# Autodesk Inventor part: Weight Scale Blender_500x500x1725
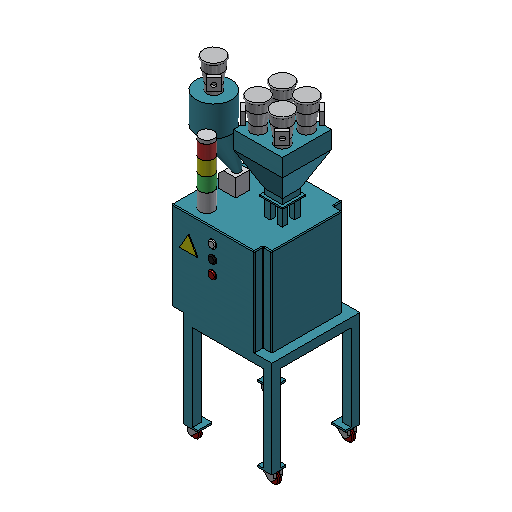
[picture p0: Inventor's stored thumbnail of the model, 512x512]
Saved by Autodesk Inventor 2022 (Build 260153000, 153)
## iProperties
RuleStatus: InUse
Created: 2013-08
Material: 一般
Document SubType Name: Modeling
Density: 1 g/cm^3
Appearance: 既定
Part Number: Weight Scale Blender_500x500x1725
Key Parameters: Length=500.000 mm;Width=500.000 mm;Height=1725.000 mm;
Author: Autodesk, Inc.
Title: Weight Scale Blender
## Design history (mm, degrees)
sketch "Sketch1"
  geometry: L1 (250, -250)-(-250, -250); L2 (-250, -250)-(-250, 250); L3 (-250, 250)-(250, 250); L4 (250, 250)-(250, -250); L5 (250, -250)-(-250, 250); L6 (-250, -250)-(250, 250); L7 (250, -250)-(170, -250); L8 (170, -250)-(170, -170); L9 (170, -170)-(250, -170); L10 (250, -170)-(250, -250); L11 (-250, -250)-(-170, -250); L12 (-170, -250)-(-170, -170); L13 (-170, -170)-(-250, -170); L14 (-250, -170)-(-250, -250); L15 (250, 250)-(170, 250); L16 (170, 250)-(170, 170); L17 (170, 170)-(250, 170); L18 (250, 170)-(250, 250); L19 (-250, 250)-(-170, 250); L20 (-170, 250)-(-170, 170); L21 (-170, 170)-(-250, 170); L22 (-250, 170)-(-250, 250); L23 (-350, 0)-(350, 0) reference; L24 (0, -1400)-(0, 1400) reference; 2 further points
  constraints: 44 end point, 10 parallel, 5 horizontal, 5 midpoint, 5 perpendicular
  dimensions: "d6" = 500 distance of L2.end L3.end (derived); "d7" = 500 distance of L1.end L2.end (derived); "d8" = 80 distance of L7.end L8.end; "d9" = 80 distance of L8.end L9.end; "d10" = 80 distance of L16.end L17.end; "d11" = 80 distance of L15.end L16.end; "d12" = 80 distance of L19.end L20.end; "d13" = 80 distance of L20.end L21.end; "d14" = 80 distance of L12.end L13.end; "d15" = 80 distance of L11.end L12.end
extrude "Extrusion1" new body sketch "Sketch1" distance "d16" = 10; taper "d17" = 0 deg
sketch "Sketch3"
  geometry: L1 (-250, -250)-(-170, -250) reference; L2 (-170, -250)-(-170, -170) reference; L3 (-170, -170)-(-250, -170) reference; L4 (-250, -170)-(-250, -250) reference; L5 (250, -250)-(170, -250) reference; L6 (250, -170)-(250, -250) reference; L7 (170, -170)-(250, -170) reference; L8 (170, -250)-(170, -170) reference; L9 (250, 250)-(170, 250) reference; L10 (170, 250)-(170, 170) reference; L11 (170, 170)-(250, 170) reference; L12 (250, 170)-(250, 250) reference; L13 (-250, 250)-(-200, 250); L14 (-200, 250)-(-200, 200); L15 (-200, 200)-(-250, 200); L16 (-250, 200)-(-250, 250); L17 (-250, -250)-(-200, -250); L18 (-200, -250)-(-200, -200); L19 (-200, -200)-(-250, -200); L20 (-250, -200)-(-250, -250); L21 (250, -250)-(200, -250); L22 (200, -250)-(200, -200); L23 (200, -200)-(250, -200); L24 (250, -200)-(250, -250); L25 (250, 250)-(200, 250); L26 (200, 250)-(200, 200); L27 (200, 200)-(250, 200); L28 (250, 200)-(250, 250); 1 further point
  constraints: 32 end point, 8 parallel, 4 horizontal, 4 perpendicular
  dimensions: "d18" = 50 distance of L22.end L23.end; "d19" = 50 distance of L21.end L22.end; "d20" = 50 distance of L26.end L27.end; "d21" = 50 distance of L25.end L26.end; "d22" = 50 distance of L14.end L15.end; "d23" = 50 distance of L13.end L14.end; "d24" = 50 distance of L18.end L19.end; "d25" = 50 distance of L17.end L18.end
extrude "Extrusion2" join sketch "Sketch3" distance "d26" = 500 (derived); taper "d27" = 0 deg
sketch "Sketch4"
  geometry: L1 (250, 250)-(200, 250) reference; L2 (200, 250)-(200, 200) reference; L3 (200, 200)-(250, 200) reference; L4 (250, 200)-(250, 250) reference; L5 (-250, -250)-(250, -250); L6 (250, -250)-(250, 250); L7 (250, 250)-(-250, 250); L8 (-250, 250)-(-250, -250); 1 further point
  constraints: 8 end point, 2 parallel, 1 horizontal, 1 perpendicular
extrude "Extrusion3" join sketch "Sketch4" distance "d28" = 50; taper "d29" = 0 deg
sketch "Sketch8"
  geometry: L1 (-250, -250)-(250, -250) reference; L2 (250, -250)-(250, 250) reference; L3 (250, 250)-(-250, 250) reference; L4 (-250, 250)-(-250, -250) reference; L5 (-320, 250)-(200, 250); L6 (200, 250)-(200, -250); L7 (200, -250)-(-320, -250); L8 (-320, -250)-(-320, 250); 1 further point
  constraints: 8 end point, 2 parallel, 1 collinear, 1 horizontal, 1 perpendicular, 1 point on line
  dimensions: "d30" = 70 distance between parallel lines of L8 L4; "d31" = 50 distance between parallel lines of L6 L2
extrude "Extrusion4" join sketch "Sketch8" distance "d32" = 500; taper "d33" = 0 deg
sketch "Sketch9"
  geometry: L1 (200, 250)-(150, 250); L2 (150, 250)-(150, 200); L3 (150, 200)-(200, 200); L4 (200, 200)-(200, 250); L5 (200, -250)-(150, -250); L6 (150, -250)-(150, -200); L7 (150, -200)-(200, -200); L8 (200, -200)-(200, -250); 1 further point
  constraints: 16 end point, 4 parallel, 2 horizontal, 2 perpendicular
  dimensions: "d34" = 50 distance of L2.end L3.end; "d35" = 50 distance of L1.end L2.end; "d36" = 50 distance of L6.end L7.end; "d37" = 50 distance of L5.end L6.end
extrude "Extrusion5" cut sketch "Sketch9" stored distance "d38" = 500000; taper "d39" = 0 deg
fillet "Fillet1" dims "d40" = 5
sketch "Sketch10"
  geometry: L1 (395, 1045)-(395, 550) reference; L2 (-65, 1045)-(395, 1045) reference; L3 (500, 0)-(500, 550) reference; L4 (165, 1045)-(165, 550); L5 (-65, 550)-(395, 550); C1 r 22.5 at (165, 970); C2 r 22.5 at (165, 895); C3 r 22.5 at (165, 820); 1 further point
  constraints: 4 end point, 3 centre point, 3 point on line, 2 midpoint, 2 parallel, 1 perpendicular
  dimensions: "d41" = 45 diameter of C1; "d42" = 45 diameter of C2; "d43" = 45 diameter of C3; "d44" = 75 distance from line of C1.centre L2; "d45" = 75 distance of C1.centre C2.centre; "d46" = 75 distance of C2.centre C3.centre
extrude "Extrusion6" join sketch "Sketch10" distance "d47" = 10; taper "d48" = 0 deg
extrude "Extrusion7" join sketch "Sketch10" distance "d49" = 10; taper "d50" = 0 deg
extrude "Extrusion8" join sketch "Sketch10" distance "d51" = 10; taper "d52" = 0 deg
fillet "Fillet2" dims "d53" = 5
fillet "Fillet3" dims "d54" = 5
fillet "Fillet4" dims "d55" = 5
sketch "Sketch11"
  geometry: L1 (-315, -245)-(-315, 245) reference; L2 (195, 195)-(195, -195) reference; L3 (-315, 0)-(195, 0); L4 (10, 50)-(110, 50); L5 (110, 50)-(110, -50); L6 (110, -50)-(10, -50); L7 (10, -50)-(10, 50); L8 (10, 50)-(110, -50); L9 (110, 50)-(10, -50); 2 further points
  constraints: 14 end point, 4 midpoint, 2 parallel, 1 horizontal, 1 perpendicular, 1 point on line
  dimensions: "d56" = 100 distance of L4.start L4.end; "d57" = 100 distance of L4.end L5.end; "d58" = 85 distance between parallel lines of L5 L2
extrude "Extrusion9" join sketch "Sketch11" distance "d59" = 110; taper "d60" = 0 deg
sketch "Sketch12"
  geometry: L1 (110, 50)-(10, 50) reference; L2 (10, 50)-(10, -50) reference; L3 (10, -50)-(110, -50) reference; L4 (110, -50)-(110, 50) reference; L5 (-5, 65)-(125, 65); L6 (125, 65)-(125, -65); L7 (125, -65)-(-5, -65); L8 (-5, -65)-(-5, 65); 1 further point
  constraints: 8 end point, 3 other
  dimensions: "d61" = 15 distance between parallel lines of L1 L5
extrude "Extrusion10" join sketch "Sketch12" distance "d62" = 8; taper "d63" = 0 deg
sketch "Sketch13"
  geometry: L1 (-5, 65)-(125, 65) reference; L2 (-5, -65)-(-5, 65) reference; L3 (125, -65)-(-5, -65) reference; L4 (125, 65)-(125, -65) reference; L5 (110, 50)-(10, 50); L6 (10, 50)-(10, -50); L7 (10, -50)-(110, -50); L8 (110, -50)-(110, 50); 1 further point
  constraints: 8 end point, 3 other
  dimensions: "d64" = 15 distance between parallel lines of L1 L5
extrude "Extrusion11" join sketch "Sketch13" distance "d65" = 30; taper "d66" = 0 deg
sketch "Sketch14"
  geometry: L1 (110, 50)-(10, 50) reference; L2 (10, 50)-(10, -50) reference; L3 (10, -50)-(110, -50) reference; L4 (110, -50)-(110, 50) reference; 1 further point
extrude "Extrusion12" join sketch "Sketch14" distance "d67" = 190.8125; taper "d68" = 25 deg
sketch "Sketch15"
  geometry: L1 (198.977, 138.977)-(198.977, -138.977) reference; L2 (-78.977, 138.977)-(198.977, 138.977) reference; L3 (-78.977, -138.977)-(-78.977, 138.977) reference; L4 (198.977, -138.977)-(-78.977, -138.977) reference; 1 further point
extrude "Extrusion13" join sketch "Sketch15" distance "d69" = 100; taper "d70" = 0 deg
sketch "Sketch16"
  geometry: L1 (110, 50)-(110, -50) reference; L2 (110, -50)-(10, -50) reference; L3 (10, -50)-(10, 50) reference; L4 (10, 50)-(110, 50) reference; L5 (155, 195)-(195, 195) reference; L6 (80, 50)-(80, 20); L7 (80, 20)-(110, 20); L8 (110, 20)-(110, -20); L9 (110, -20)-(80, -20); L10 (80, -20)-(80, -50); L11 (80, -50)-(40, -50); L12 (40, -50)-(40, -20); L13 (40, -20)-(10, -20); L14 (10, -20)-(10, 20); L15 (10, 20)-(40, 20); L16 (40, 20)-(40, 50); L17 (40, 50)-(80, 50); 1 further point
  constraints: 24 end point, 8 perpendicular, 8 point on line, 1 collinear
  dimensions: "d71" = 30 distance between parallel lines of L7 L4; "d72" = 30 distance between parallel lines of L2 L9; "d73" = 30 distance between parallel lines of L1 L10; "d74" = 30 distance between parallel lines of L3 L12; "d75" = 30 distance between parallel lines of L2 L13; "d76" = 30 distance between parallel lines of L4 L15; "d77" = 30 distance between parallel lines of L3 L16; "d78" = 30 distance between parallel lines of L1 L6
extrude "Extrusion14" cut sketch "Sketch16" stored distance "d79" = 114.2875; taper "d80" = 0 deg
sketch "Sketch17"
  geometry: L1 (-315, -245)-(-315, 245) reference; L2 (155, 195)-(195, 195) reference; L3 (-315, 0)-(-37.685, 0); L4 (-265, 40)-(-165, 40); L5 (-165, 40)-(-165, -40); L6 (-165, -40)-(-265, -40); L7 (-265, -40)-(-265, 40); L8 (-265, 40)-(-165, -40); L9 (-165, 40)-(-265, -40); 2 further points
  constraints: 14 end point, 3 midpoint, 3 parallel, 1 horizontal, 1 perpendicular, 1 point on line
  dimensions: "d81" = 100 distance of L4.start L4.end; "d82" = 80 distance of L4.end L5.end; "d83" = 50 distance between parallel lines of L1 L7
extrude "Extrusion15" join sketch "Sketch17" distance "d84" = 100; taper "d85" = 0 deg
chamfer "Chamfer1" distance "d86" = 30; stored, may be unused: second distance "d87" = 2, angle "d88" = 45 deg
sketch "Sketch18"
  geometry: L1 (-235, -40)-(-235, 40) reference; L2 (-235, 0)-(-165, 0); C1 r 22.5 at (-200, 0); 5 further points; 1 other entity
  constraints: 2 end point, 2 midpoint, 1 centre point, 2 other
  dimensions: "d89" = 45 diameter of C1
workplane "Work Plane1"
sketch "Sketch19"
  geometry: L1 (-200, 0)-(-594.488, 0); L2 (-320, 245)-(-320, -245) reference; C1 r 22.5 at (-200, 0) reference; C2 r 100 at (-330, 0); 1 further point
  constraints: 2 end point, 1 centre point, 1 horizontal, 1 point on line
  dimensions: "d91" = 200 diameter of C2; "d92" = 10 distance from line of L2 C2.centre
loft "Loft1" sketch "Sketch19" dims "d93" = 0, "d94" = 90 deg, "d95" = 0, "d96" = 90 deg
sketch "Sketch20"
  geometry: C1 r 100 at (0, 0) reference; 1 further point
extrude "Extrusion16" join sketch "Sketch20" stored distance "d97" = 150; taper "d98" = 0 deg
sketch "Sketch21"
  geometry: L1 (198.977, -138.977)-(198.977, 138.977) reference; L2 (198.977, 138.977)-(-78.977, 138.977) reference; L3 (-78.977, 138.977)-(-78.977, -138.977) reference; L4 (-78.977, -138.977)-(198.977, -138.977) reference; C1 r 40 at (-8.977, 68.977); C2 r 40 at (128.977, 68.977); C3 r 40 at (-8.977, -68.977); C4 r 40 at (128.977, -68.977); C5 r 100 at (-330, 0) reference; C6 r 40 at (-330, 0); 1 further point
  constraints: 5 centre point, 1 coincident
  dimensions: "d99" = 70 distance from line of L2 C1.centre; "d100" = 70 distance from line of L3 C1.centre; "d101" = 70 distance from line of L2 C2.centre; "d102" = 70 distance from line of L1 C2.centre; "d103" = 70 distance from line of L3 C3.centre; "d104" = 70 distance from line of L4 C3.centre; "d105" = 70 distance from line of L4 C4.centre; "d106" = 70 distance from line of L1 C4.centre; "d107" = 80 diameter of C1; "d108" = 80 diameter of C2; "d109" = 80 diameter of C3; "d110" = 80 diameter of C4; "d128" = 80 diameter of C6
extrude "Extrusion17" join sketch "Sketch21" distance "d111" = 40; taper "d112" = 0 deg
sketch "Sketch22"
  geometry: C1 r 40 at (0, 0) reference; C2 r 40 at (137.955, 0) reference; C3 r 40 at (0, -137.955) reference; C4 r 40 at (137.955, -137.955) reference; C5 r 40 at (-321.023, -68.977) reference; 1 further point
extrude "Extrusion18" join sketch "Sketch22" distance "d113" = 70; taper "d114" = 10 deg
sketch "Sketch23"
  geometry: C1 r 52.343 at (0, 0) reference; C2 r 52.343 at (137.955, 0) reference; C3 r 52.343 at (0, -137.955) reference; C4 r 52.343 at (137.955, -137.955) reference; C5 r 40 at (-321.023, -68.977) reference; C6 r 52.343 at (-321.023, -68.977) reference; 1 further point
extrude "Extrusion19" join sketch "Sketch23" distance "d115" = 60; taper "d116" = 0 deg
sketch "Sketch24"
  geometry: C1 r 52.343 at (0, 0) reference; C2 r 52.343 at (-137.955, 0) reference; C3 r 52.343 at (-137.955, -137.955) reference; C4 r 52.343 at (0, -137.955) reference; C5 r 62.343 at (-137.955, 0); C6 r 62.343 at (0, 0); C7 r 62.343 at (0, -137.955); C8 r 62.343 at (-137.955, -137.955); C9 r 52.343 at (-458.977, -68.977) reference; C10 r 62.343 at (-458.977, -68.977); 1 further point
  constraints: 5 centre point
  dimensions: "d117" = 10 radial gap between concentric circles of C2 C5; "d118" = 10 radial gap between concentric circles of C1 C6; "d119" = 10 radial gap between concentric circles of C4 C7; "d120" = 10 radial gap between concentric circles of C3 C8; "d129" = 10 radial gap between concentric circles of C9 C10
extrude "Extrusion20" join sketch "Sketch24" distance "d121" = 10; taper "d122" = 0 deg
sketch "Sketch25"
  geometry: L1 (500, 0)-(500, 550) reference; L2 (30, 950)-(-20, 863.397); L3 (-20, 863.397)-(80, 863.397); L4 (80, 863.397)-(30, 950); L5 (395, 1050)-(-65, 1050) reference; L6 (-70, 1045)-(-70, 550) reference; 1 further point
  constraints: 6 end point, 2 equal length, 1 perpendicular
  dimensions: "d123" = 100 distance of L2.end L3.end; "d124" = 100 distance from line of L5 L2.start; "d125" = 50 distance from line of L6 L2.end
extrude "Extrusion21" join sketch "Sketch25" distance "d126" = 5; taper "d127" = 0 deg
sketch "Sketch26"
  geometry: L1 (-320, 245)-(-320, -245) reference; L2 (-315, -250)-(145, -250) reference; C1 r 40 at (-200, -170); 1 further point
  constraints: 1 centre point
  dimensions: "d130" = 80 diameter of C1; "d131" = 120 distance from line of L1 C1.centre; "d132" = 80 distance from line of L2 C1.centre
extrude "Extrusion22" join sketch "Sketch26" distance "d133" = 100; taper "d134" = 0 deg
sketch "Sketch27"
  geometry: C1 r 40 at (0, 0) reference; 1 further point
extrude "Extrusion23" new body sketch "Sketch27" distance "d135" = 80; taper "d136" = 0 deg
sketch "Sketch28"
  geometry: C1 r 40 at (0, 0) reference; 1 further point
extrude "Extrusion24" new body sketch "Sketch28" distance "d137" = 80; taper "d138" = 0 deg
sketch "Sketch29"
  geometry: C1 r 40 at (0, 0) reference; 1 further point
extrude "Extrusion25" new body sketch "Sketch29" distance "d139" = 80; taper "d140" = 0 deg
sketch "Sketch30"
  geometry: C1 r 40 at (0, 0) reference; 1 further point
extrude "Extrusion26" new body sketch "Sketch30" distance "d141" = 20; taper "d142" = 0 deg
fillet "Fillet5" dims "d143" = 5
workplane "Work Plane2"
sketch "Sketch31"
  geometry: L1 (144.776, -127.203)-(187.203, -84.776); L2 (187.203, -84.776)-(201.345, -98.918); L3 (201.345, -98.918)-(158.918, -141.345); L4 (158.918, -141.345)-(144.776, -127.203); L5 (144.776, 127.203)-(187.203, 84.776); L6 (187.203, 84.776)-(201.345, 98.918); L7 (201.345, 98.918)-(158.918, 141.345); L8 (158.918, 141.345)-(144.776, 127.203); L9 (-314.201, -58.225)-(-271.775, -15.799); L10 (-271.775, -15.799)-(-257.633, -29.941); L11 (-257.633, -29.941)-(-300.059, -72.367); L12 (-300.059, -72.367)-(-314.201, -58.225); L13 (128.977, -68.977)-(282.8, -222.8); L14 (128.977, 68.977)-(242.144, 182.144); L15 (-8.977, 68.977)-(-133.35, 193.35); L16 (-8.977, -68.977)-(-76.387, -136.387); L17 (250, 250)-(145, 250) reference; L18 (145, 250)-(-315, 250) reference; L19 (-315, -250)-(145, -250) reference; L20 (-330, 0)-(-221.248, -108.752); L21 (-38.918, 141.345)-(-81.345, 98.918); L22 (-81.345, 98.918)-(-67.203, 84.776); L23 (-67.203, 84.776)-(-24.776, 127.203); L24 (-24.776, 127.203)-(-38.918, 141.345); L25 (-67.203, -84.776)-(-81.345, -98.918); L26 (-81.345, -98.918)-(-38.918, -141.345); L27 (-38.918, -141.345)-(-24.776, -127.203); L28 (-24.776, -127.203)-(-67.203, -84.776); C1 r 52.343 at (128.977, -68.977) reference; C2 r 40 at (128.977, -68.977) reference; C3 r 52.343 at (-8.977, -68.977) reference; C4 r 40 at (-8.977, -68.977) reference; C5 r 52.343 at (128.977, 68.977) reference; C6 r 40 at (128.977, 68.977) reference; C7 r 40 at (-8.977, 68.977) reference; C8 r 52.343 at (-8.977, 68.977) reference; C9 r 40 at (-8.977, 68.977) reference; C10 r 52.343 at (-330, 0) reference; C11 r 40 at (-330, 0) reference; 1 further point
  constraints: 50 end point, 10 parallel, 6 perpendicular, 5 tangent, 5 other
  dimensions: "d145" = 135 deg angle of L17 L14; "d146" = 45 deg angle of L18 L15; "d147" = 45 deg angle of L19 L16; "d148" = 45 deg angle of L19 L20; "d149" = 60 distance of L21.start L21.end; "d150" = 20 distance of L23.end L21.start; "d151" = 20 distance of L9.end L10.end; "d152" = 60 distance of L10.end L11.end; "d155" = 60 distance of L25.end L26.end; "d156" = 20 distance of L25.start L25.end; "d157" = 20 distance of L7.end L5.start; "d158" = 60 distance of L6.end L7.end; "d159" = 20 distance of L3.end L1.start; "d160" = 60 distance of L2.end L3.end
extrude "Extrusion27" join sketch "Sketch31" distance "d161" = 70; taper "d162" = 0 deg
sketch "Sketch32"
  geometry: L1 (0, 0)-(-60, 0) reference; L2 (-60, 70)-(0, 70) reference; L3 (-30, 70)-(-30, 0); C1 r 12.5 at (-30, 35); 1 further point
  constraints: 3 midpoint, 2 end point, 1 centre point
  dimensions: "d163" = 25 diameter of C1
extrude "Extrusion28" cut sketch "Sketch32" distance "d164" = 15; taper "d165" = 0 deg
sketch "Sketch34"
  geometry: L1 (-60, 0)-(0, 0) reference; L2 (-60, 70)-(0, 70) reference; L3 (-30, 70)-(-30, 0); C1 r 12.5 at (-30, 35); 1 further point
  constraints: 3 midpoint, 2 end point, 1 centre point
  dimensions: "d166" = 25 diameter of C1
extrude "Extrusion29" cut sketch "Sketch34" distance "d167" = 15; taper "d168" = 0 deg
sketch "Sketch35"
  geometry: L1 (-60, 0)-(0, 0) reference; L2 (-60, 70)-(0, 70) reference; L3 (-30, 70)-(-30, 0); C1 r 12.5 at (-30, 35); 1 further point
  constraints: 3 midpoint, 2 end point, 1 centre point
  dimensions: "d169" = 25 diameter of C1
extrude "Extrusion30" cut sketch "Sketch35" distance "d170" = 15; taper "d171" = 0 deg
sketch "Sketch36"
  geometry: L1 (-60, 0)-(0, 0) reference; L2 (-60, 70)-(0, 70) reference; L3 (-30, 70)-(-30, 0); C1 r 12.5 at (-30, 35); 1 further point
  constraints: 3 midpoint, 2 end point, 1 centre point
  dimensions: "d172" = 25 diameter of C1
extrude "Extrusion31" cut sketch "Sketch36" distance "d173" = 15; taper "d174" = 0 deg
sketch "Sketch37"
  geometry: L1 (0, 0)-(-60, 0) reference; L2 (-60, 70)-(0, 70) reference; L3 (-30, 70)-(-30, 0); C1 r 12.5 at (-30, 35); 1 further point
  constraints: 3 midpoint, 2 end point, 1 centre point
  dimensions: "d175" = 25 diameter of C1
extrude "Extrusion32" cut sketch "Sketch37" distance "d176" = 15; taper "d177" = 0 deg
workplane "Work Plane3"
sketch "Sketch40"
  geometry: L1 (-250, 170)-(-250, 250) reference; L2 (-170, 170)-(-250, 170) reference; L3 (-170, 250)-(-170, 170) reference; L4 (-250, 250)-(-170, 250) reference; L5 (-170, -250)-(-170, -170) reference; L6 (-170, -170)-(-250, -170) reference; L7 (-250, -170)-(-250, -250) reference; L8 (-250, -250)-(-170, -250) reference; L9 (170, -250)-(170, -170) reference; L10 (250, -170)-(250, -250) reference; L11 (170, -170)-(250, -170) reference; L12 (170, -250)-(170, -170) reference; L13 (250, -250)-(170, -250) reference; L14 (250, 250)-(170, 250) reference; L15 (170, 250)-(170, 170) reference; L16 (170, 170)-(250, 170) reference; L17 (250, 170)-(250, 250) reference; L18 (-245, 235)-(-175, 235); L19 (-175, 235)-(-175, 185); L20 (-175, 185)-(-245, 185); L21 (-245, 185)-(-245, 235); L22 (175, 235)-(245, 235); L23 (245, 235)-(245, 185); L24 (245, 185)-(175, 185); L25 (175, 185)-(175, 235); L26 (-245, -185)-(-175, -185); L27 (-175, -185)-(-175, -235); L28 (-175, -235)-(-245, -235); L29 (-245, -235)-(-245, -185); L30 (175, -185)-(245, -185); L31 (245, -185)-(245, -235); L32 (245, -235)-(175, -235); L33 (175, -235)-(175, -185); 1 further point
  constraints: 32 end point, 8 parallel, 4 horizontal, 4 perpendicular
  dimensions: "d179" = 15 distance between parallel lines of L4 L18; "d180" = 15 distance between parallel lines of L2 L20; "d181" = 15 distance between parallel lines of L6 L26; "d182" = 15 distance between parallel lines of L8 L28; "d183" = 15 distance between parallel lines of L13 L32; "d184" = 15 distance between parallel lines of L11 L30; "d185" = 15 distance between parallel lines of L14 L22; "d186" = 15 distance between parallel lines of L16 L24; "d187" = 5 distance between parallel lines of L1 L21; "d188" = 5 distance between parallel lines of L3 L19; "d189" = 5 distance between parallel lines of L7 L29; "d190" = 5 distance between parallel lines of L5 L27; "d196" = 5 distance between parallel lines of L15 L25; "d197" = 5 distance between parallel lines of L17 L23; "d198" = 5 distance between parallel lines of L9 L33; "d199" = 5 distance between parallel lines of L10 L31
extrude "Extrusion33" join sketch "Sketch40" distance "d191" = 50; taper "d192" = 0 deg
sketch "Sketch41"
  geometry: L1 (0, 0)-(0, -50) reference; L2 (70, -50)-(0, -50) reference; L3 (70, 0)-(70, -50) reference; L4 (70, -5)-(25, -50); L5 (0, -30)-(0, -50); L6 (0, -50)-(20, -50); L7 (25, -50)-(70, -50); L8 (70, -50)-(70, -5); L9 (45, 500)-(445, 500) reference; L10 (245, 500)-(245, 278.52); L11 (420, -50)-(490, -50); L12 (420, -5)-(465, -50); L13 (490, -30)-(490, -50); L14 (490, -50)-(470, -50); L15 (465, -50)-(420, -50); L16 (420, -50)-(420, -5); A1 r 20 centre (20, -30) between (0, -30) and (20, -50); A2 r 20 centre (470, -30) between (470, -50) and (490, -30); 1 further point
  constraints: 24 end point, 7 symmetric about line, 6 point on line, 4 point on circle, 3 collinear, 3 tangent, 2 centre point, 1 midpoint, 1 perpendicular, 1 other
  dimensions: "d193" = 45 deg angle of L2 L4; "d194" = 20 radius of A1; "d195" = 45 distance from line of L3 L4.end
extrude "Extrusion34" cut sketch "Sketch41" stored distance "d200" = 40; taper "d201" = 0 deg
workplane "Work Plane4"
sketch "Sketch42"
  geometry: L1 (30, -50)-(75, -5) reference; L2 (75, 0)-(75, -5) reference; L3 (5, 0)-(75, 0) reference; L4 (5, 0)-(5, -30) reference; L5 (30, -50)-(25, -50) reference; L6 (425, -5)-(470, -50) reference; L7 (475, -50)-(470, -50) reference; L8 (495, 0)-(495, -30) reference; L9 (425, 0)-(495, 0) reference; L10 (425, 0)-(425, -5) reference; A1 r 20 centre (25, -30) between (5, -30) and (25, -50) reference; A2 r 20 centre (475, -30) between (475, -50) and (495, -30) reference
extrude "Extrusion35" cut sketch "Sketch42" stored distance "d202" = 20; taper "d203" = 0 deg
sketch "Sketch43"
  geometry: L1 (50, -50)-(5, -5) reference; L2 (5, 0)-(5, -5) reference; L3 (75, 0)-(5, 0) reference; L4 (75, 0)-(75, -30) reference; L5 (50, -50)-(55, -50) reference; L6 (-345, -5)-(-390, -50) reference; L7 (-395, -50)-(-390, -50) reference; L8 (-415, 0)-(-415, -30) reference; L9 (-345, 0)-(-415, 0) reference; L10 (-345, 0)-(-345, -5) reference; A1 r 20 centre (55, -30) between (55, -50) and (75, -30) reference; A2 r 20 centre (-395, -30) between (-415, -30) and (-395, -50) reference; 1 further point
extrude "Extrusion36" cut sketch "Sketch43" stored distance "d204" = 20; taper "d205" = 0 deg
sketch "Sketch44"
  geometry: L1 (-435.338, -74.187)-(-295.884, -74.187); L2 (-420, 0)-(-340, 0) reference; L3 (-395, -30)-(-395, -64.93); L4 (55, -30)-(55, -50); L5 (8.857, -75)-(93.349, -75); L6 (5, 0)-(75, 0) reference; C1 r 34.187 at (-395, -40); C2 r 35 at (55, -40); A1 r 20 centre (-395, -30) between (-415, -30) and (-395, -50) reference; A2 r 20 centre (55, -30) between (55, -50) and (75, -30) reference; 1 further point
  constraints: 8 end point, 2 centre point, 2 midpoint, 2 perpendicular, 2 tangent, 1 horizontal, 1 parallel, 1 point on line
  dimensions: "d206" = 10 distance of C1.centre L3.start; "d208" = 74.187 distance between parallel lines of L2 L1; "d209" = 75 distance between parallel lines of L6 L5; "d210" = 10 distance of C2.centre L4.start
extrude "Extrusion37" join sketch "Sketch44" stored distance "d211" = 20; taper "d212" = 0 deg
sketch "Sketch45"
  geometry: L1 (25, -30)-(25, -63.901); L2 (475, -30)-(475, -60.52); L3 (-9.385, -74.187)-(60.236, -74.187); L4 (5, 0)-(75, 0) reference; L5 (-137.343, 1650.812)-(-22.657, 1650.812) reference; L6 (0, 550)-(-65, 550) reference; L7 (50, 500)-(450, 500) reference; C1 r 34.187 at (25, -40); C2 r 34.187 at (475, -40); A1 r 20 centre (25, -30) between (5, -30) and (25, -50) reference; A2 r 20 centre (475, -30) between (475, -50) and (495, -30) reference; 1 further point
  constraints: 6 end point, 2 centre point, 2 point on line, 2 tangent, 1 parallel, 1 perpendicular, 1 vertical
  dimensions: "d213" = 10 distance of C1.centre L1.start; "d214" = 10 distance of C2.centre L2.start; "d222" = 74.187 distance between parallel lines of L4 L3
extrude "Extrusion38" join sketch "Sketch45" stored distance "d216" = 20; taper "d217" = 0 deg
fillet "Fillet6" dims "d218" = 5
workplane "Work Plane5"
node "Landing Surface"
body "Solid1"
node "Projected Loop1"
node "Projected Loop2"
node "Projected Loop3"
node "Projected Loop4"
node "Projected Loop5"
node "Projected Loop6"
node "Projected Loop7"
node "Projected Loop8"
node "Projected Loop9"
body "Solid2"
body "Solid3"
body "Solid4"
body "Solid5"
node "Projected Loop10"
node "Projected Loop11"
node "Projected Loop12"
node "Projected Loop13"
node "Projected Loop14"
node "Projected Loop17"
node "Projected Loop18"
node "Projected Loop19"
node "Projected Loop20"
node "Projected Loop21"
node "Projected Loop22"
